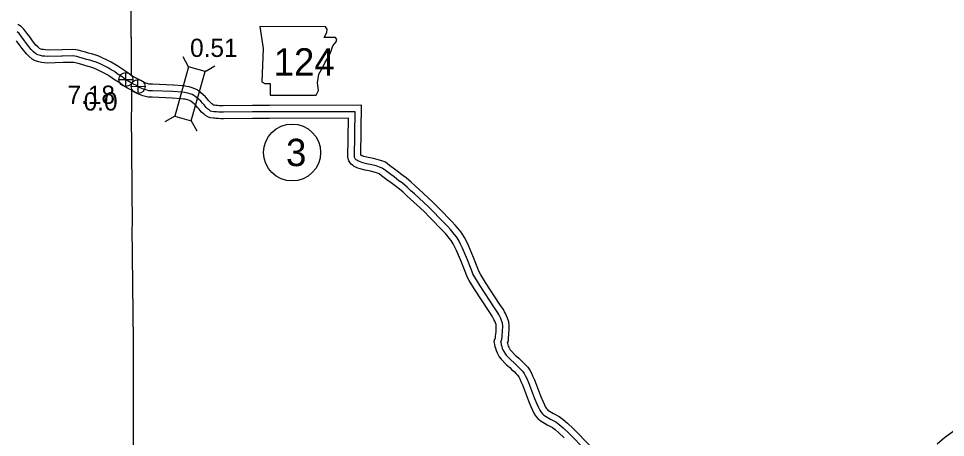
# Model space of a CAD drawing. Extents: x -83719 to 153526, y -11835 to 11446.
# Drawn here: x -664 to 52, y 1735 to 2059 of the extents above; entities that cross this region are included whole.
import ezdxf

# ---------------------------------------------------------------- set-up
doc = ezdxf.new("R2010")
doc.units = 0
for name, color, linetype in [('Level 10', 7, 'Continuous'), ('Level 11', 7, 'Continuous'), ('Level 2', 7, 'Continuous'), ('Level 20', 7, 'Continuous'), ('Level 21', 7, 'Continuous'), ('Level 25', 7, 'Continuous'), ('Level 26', 7, 'Continuous'), ('Level 27', 7, 'Continuous'), ('Level 58', 7, 'Continuous'), ('Level 59', 7, 'Continuous')]:
    doc.layers.add(name, color=color, linetype=linetype)

msp = doc.modelspace()

# ---------------------------------------------------------------- linework, layer by layer
at = {"layer": 'Level 10'}
for points in [[(-544.58, 2007.5), (-560.5, 2008.16), (-562.13, 2008.16), (-562.73, 2008.19), (-563.35, 2008.32), (-564.67, 2008.77), (-565.63, 2009.11), (-567.8, 2009.99), (-570.53, 2011.7), (-573.07, 2012.87), (-575.05, 2013.83), (-576.74, 2014.88)], [(-483.28, 1991.81), (-505.85, 1991.53), (-507.4, 1991.51), (-508.95, 1991.6), (-510.41, 1991.73), (-511.57, 1991.88), (-512.66, 1991.96), (-513.51, 1992.08), (-513.94, 1992.47), (-514.78, 1993.14), (-515.54, 1993.78), (-515.98, 1994.29), (-516.91, 1995.49), (-518.21, 1996.86), (-519.69, 1998.58), (-521.59, 2000.3), (-523.19, 2001.65), (-524.7, 2002.81), (-525.99, 2003.87), (-527.9, 2004.74), (-529.86, 2005.52), (-532.16, 2006.17), (-533.91, 2006.48), (-535.24, 2006.64), (-537.28, 2006.93), (-544.39, 2007.49)], [(-545, 1997.51), (-560.71, 1998.16), (-562.34, 1998.16), (-563.94, 1998.23), (-566, 1998.65), (-567.97, 1999.33), (-569.16, 1999.75), (-572.36, 2001.04), (-575.31, 2002.89), (-576.63, 2003.5)], [(-483.15, 1981.81), (-505.72, 1981.53), (-507.63, 1981.5), (-509.69, 1981.63), (-511.5, 1981.78), (-512.61, 1981.93), (-513.73, 1982.02), (-515.84, 1982.31), (-517.81, 1982.93), (-519.66, 1984.15), (-520.44, 1984.87), (-521.08, 1985.38), (-522.61, 1986.64), (-523.74, 1987.98), (-524.5, 1988.96), (-525.64, 1990.16), (-526.88, 1991.6), (-528.16, 1992.77), (-529.46, 1993.85), (-530.92, 1994.98), (-531.31, 1995.3), (-531.83, 1995.54), (-533.08, 1996.04), (-534.4, 1996.41), (-535.39, 1996.59), (-536.53, 1996.73), (-538.37, 1996.98), (-545.18, 1997.52)], [(-286.36, 1808.44), (-285.64, 1810.12), (-285.53, 1812.53), (-285.34, 1814.29), (-285.18, 1816.04), (-285.08, 1818.1), (-284.95, 1819.78), (-285.06, 1821.67), (-285.23, 1824.52), (-286.23, 1827.42), (-287.06, 1829.24), (-287.87, 1831), (-288.67, 1832.4), (-289.43, 1834.03), (-292.32, 1838.07), (-303.25, 1855.06), (-307.22, 1861.51), (-308.48, 1863.71), (-309.3, 1865.88), (-310.84, 1869.66), (-312.68, 1874.31), (-316.48, 1883.64), (-318.04, 1886.89), (-319.61, 1889.82), (-321.57, 1892.96), (-323.21, 1895.19), (-326.69, 1899.34), (-328.98, 1901.81), (-332.1, 1905.01), (-335.95, 1909.01), (-339.09, 1912.27), (-343.87, 1917.09), (-354.78, 1927.06), (-357.45, 1929.49), (-360.61, 1932.5), (-364.66, 1935.87), (-367.22, 1937.7), (-368.99, 1939), (-370.83, 1940.52), (-373.53, 1942.46), (-377.52, 1945.44), (-380.59, 1947.86), (-383.45, 1948.91), (-386.33, 1949.83), (-389.9, 1950.81), (-394.02, 1951.55), (-397.36, 1952.45), (-398.44, 1952.8), (-398.75, 1952.93), (-399.49, 1953.4), (-399.02, 1991.91), (-470.07, 1991.78), (-483.2, 1991.81)], [(-296.75, 1809.56), (-295.55, 1812.37), (-295.51, 1813.3), (-295.29, 1815.28), (-295.16, 1816.74), (-295.06, 1818.76), (-294.97, 1819.89), (-295.04, 1821.07), (-295.13, 1822.55), (-295.53, 1823.71), (-296.14, 1825.07), (-296.77, 1826.43), (-297.56, 1827.81), (-298.1, 1828.96), (-300.6, 1832.46), (-311.71, 1849.73), (-315.81, 1856.39), (-317.56, 1859.42), (-318.61, 1862.23), (-320.12, 1865.94), (-321.96, 1870.59), (-325.63, 1879.58), (-326.96, 1882.36), (-328.27, 1884.8), (-329.86, 1887.35), (-331.08, 1889.02), (-334.19, 1892.72), (-336.23, 1894.92), (-339.28, 1898.05), (-343.15, 1902.08), (-346.24, 1905.27), (-350.8, 1909.87), (-361.53, 1919.68), (-364.27, 1922.17), (-367.26, 1925.02), (-370.78, 1927.95), (-373.08, 1929.59), (-375.14, 1931.11), (-376.95, 1932.6), (-379.44, 1934.39), (-383.61, 1937.51), (-385.53, 1939.02), (-386.7, 1939.45), (-389.18, 1940.25), (-392.11, 1941.05), (-396.21, 1941.79), (-400.17, 1942.85), (-401.9, 1943.4), (-404.82, 1944.63), (-405.79, 1945.57), (-406.09, 1945.76), (-407.02, 1946.5), (-407.8, 1947.41), (-408.97, 1949.02), (-409.51, 1951.67), (-409.14, 1981.89), (-470.08, 1981.78), (-483.23, 1981.81)], [(-296.79, 1809.53), (-295.99, 1805.53), (-295.62, 1804.15), (-295.14, 1802.35), (-294.32, 1800.56), (-292.66, 1797.57), (-291.24, 1795.59), (-287.12, 1791.36), (-284.48, 1789.19), (-282.86, 1787.53), (-281.22, 1786.03), (-279.63, 1784.39), (-278.58, 1783.2), (-277.68, 1781.95), (-276.85, 1780.38), (-276.01, 1778.55), (-274.81, 1775.87), (-270.14, 1763.49), (-268.19, 1759.15), (-266.99, 1756.38), (-265.9, 1753.96), (-264.68, 1751.93), (-262.91, 1749.93), (-261.18, 1748.32), (-255.57, 1744.87), (-251.69, 1742.91), (-249.5, 1741.31), (-246.65, 1738.81), (-242.46, 1734.94)], [(-286.36, 1808.39), (-286.25, 1807.8), (-285.96, 1806.72), (-285.7, 1805.74), (-285.39, 1805.08), (-284.2, 1802.93), (-283.55, 1802.02), (-280.35, 1798.74), (-277.69, 1796.56), (-275.89, 1794.7), (-274.26, 1793.21), (-272.3, 1791.19), (-270.74, 1789.44), (-269.16, 1787.21), (-267.89, 1784.82), (-266.9, 1782.69), (-265.56, 1779.68), (-260.9, 1767.31), (-259.04, 1763.19), (-257.84, 1760.41), (-257.03, 1758.61), (-256.58, 1757.87), (-255.75, 1756.93), (-255.09, 1756.32), (-250.69, 1753.6), (-246.47, 1751.48), (-243.24, 1749.13), (-239.95, 1746.24), (-235.49, 1742.1), (-222.17, 1728.47)], [(45.47, 1730.23), (51.27, 1735.24), (69.75, 1748.55)]]:
    msp.add_lwpolyline(points, dxfattribs=at)
at = {"layer": 'Level 11'}
for points in [[(-576.63, 2014.81), (-577.13, 2015.12), (-579.64, 2017), (-581.16, 2018.1), (-584.97, 2020.5), (-587.17, 2022.08), (-589.81, 2023.69), (-592.4, 2025.29), (-596.03, 2027.07), (-598.78, 2028.42), (-602.03, 2029.79), (-604.93, 2030.88), (-607.52, 2031.61), (-610.04, 2032.25), (-612.32, 2032.95), (-615.31, 2033.8), (-617.78, 2034.4), (-619.58, 2034.76), (-622.06, 2035.06), (-630.09, 2034.9), (-641.18, 2034.61), (-643.08, 2034.78), (-644.79, 2034.95), (-645.89, 2035.16), (-647.19, 2035.55), (-647.76, 2035.87), (-649.17, 2037.08), (-650.5, 2038.34), (-653.1, 2041.66), (-655.3, 2044.78), (-657.48, 2047.67), (-659.86, 2050.83), (-661.94, 2052.69), (-664.47, 2054.26)], [(-576.45, 2003.42), (-577.34, 2003.83), (-579.88, 2005.05), (-582.79, 2006.86), (-585.56, 2008.95), (-586.75, 2009.8), (-590.56, 2012.2), (-592.7, 2013.74), (-595.05, 2015.17), (-597.25, 2016.53), (-600.42, 2018.09), (-602.92, 2019.31), (-605.73, 2020.49), (-608.06, 2021.37), (-610.1, 2021.95), (-612.74, 2022.61), (-615.16, 2023.36), (-617.86, 2024.13), (-619.95, 2024.64), (-621.16, 2024.88), (-622.55, 2025.05), (-629.86, 2024.9), (-641.49, 2024.6), (-644, 2024.82), (-646.23, 2025.04), (-648.28, 2025.43), (-651.14, 2026.3), (-653.53, 2027.65), (-655.86, 2029.64), (-657.91, 2031.58), (-661.13, 2035.69), (-663.39, 2038.89), (-665.46, 2041.66)]]:
    msp.add_lwpolyline(points, dxfattribs=at)
at = {"layer": 'Level 2'}
for points in [[(-576.62, 2016.42), (-576.93, 2073.47), (-577, 2075.21), (-577.8, 2161.28), (-577.83, 2163.01), (-578.77, 2249.01), (-578.7, 2250.72), (-579.42, 2288.6)], [(-576.61, 2015.07), (-576.93, 2073.47), (-577, 2075.21), (-577.8, 2161.28), (-577.83, 2163.01), (-578.77, 2249.01), (-578.7, 2250.72), (-579.42, 2288.6)], [(-575.21, 1721.72), (-575.14, 1809.64), (-576.15, 1897.51), (-575.94, 1898.88), (-576.63, 1985.79), (-576.46, 1987.3), (-576.55, 2003.27)], [(-575.21, 1721.72), (-575.14, 1809.64), (-576.15, 1897.51), (-575.94, 1898.88), (-576.63, 1985.79), (-576.46, 1987.3), (-576.54, 2002.28)]]:
    msp.add_lwpolyline(points, dxfattribs=at)
at = {"layer": 'Level 20'}
for p, q in [((-532.62, 2021.67), (-536.93, 2029.34)), ((-519.91, 2018.1), (-512.24, 2022.41)), ((-543.33, 1983.55), (-551, 1979.24)), ((-530.62, 1979.98), (-526.32, 1972.3))]:
    msp.add_line(p, q, dxfattribs=at)
msp.add_lwpolyline([(-532.62, 2021.67), (-543.33, 1983.55), (-530.62, 1979.98), (-519.91, 2018.1)], close=True, dxfattribs=at)
at = {"layer": 'Level 21'}
msp.add_lwpolyline([(-477.51, 2052.7), (-474.97, 2035.78), (-476.1, 2010.12), (-473.84, 2008.71), (-469.61, 2008.71), (-469.61, 1999.69), (-434.09, 1999.69), (-432.39, 2003.35), (-432.96, 2009.27), (-432.11, 2016.04), (-429.01, 2021.4), (-427.04, 2025.35), (-424.22, 2029.58), (-422.53, 2034.09), (-421.12, 2037.75), (-418.58, 2040.85), (-418.01, 2042.83), (-419.14, 2044.24), (-427.88, 2044.24), (-425.91, 2048.19), (-425.63, 2050.72), (-426.8, 2052.67)], close=True, dxfattribs=at)
at = {"layer": 'Level 26'}
for p, q in [((-586.43, 2011.85), (-575.6, 2011.85)), ((-581.02, 2006.43), (-581.02, 2017.27)), ((-571.45, 2001.03), (-571.7, 2011.88)), ((-577, 2006.33), (-566.16, 2006.58))]:
    msp.add_line(p, q, dxfattribs=at)
for centre, radius in [((-581.02, 2011.85), 5.42), ((-571.58, 2006.46), 5.43)]:
    msp.add_circle(centre, radius, dxfattribs=at)
at = {"layer": 'Level 27'}
msp.add_circle((-452.65, 1955.45), 22, dxfattribs=at)
at = {"layer": 'Level 59'}
for points in [[(-575.25, 2008.37), (-577.46, 2009.44), (-579.96, 2010.99), (-582.6, 2012.98), (-583.95, 2013.95), (-587.77, 2016.35), (-589.93, 2017.91), (-592.43, 2019.43), (-594.82, 2020.91), (-598.23, 2022.58), (-600.85, 2023.87), (-603.88, 2025.14), (-606.5, 2026.12), (-608.81, 2026.78), (-611.39, 2027.43), (-613.74, 2028.15), (-616.59, 2028.96), (-618.86, 2029.52), (-620.37, 2029.82), (-622.31, 2030.05), (-629.97, 2029.9), (-641.34, 2029.61), (-643.54, 2029.8), (-645.51, 2029.99), (-647.08, 2030.3), (-649.16, 2030.92), (-650.65, 2031.76), (-652.51, 2033.36), (-654.21, 2034.96), (-657.12, 2038.68), (-659.35, 2041.84), (-661.47, 2044.67), (-663.56, 2047.43), (-664.95, 2048.67)], [(-544.79, 2002.51), (-560.6, 2003.16), (-562.24, 2003.16), (-563.34, 2003.21), (-564.68, 2003.48), (-566.32, 2004.05), (-567.4, 2004.43), (-570.08, 2005.51), (-572.92, 2007.29), (-575.21, 2008.35), (-577.46, 2009.44), (-579.96, 2010.99), (-582.6, 2012.98), (-583.95, 2013.95), (-587.77, 2016.35), (-589.93, 2017.91), (-592.43, 2019.43), (-594.82, 2020.91), (-598.23, 2022.58), (-600.85, 2023.87), (-603.88, 2025.14), (-606.5, 2026.12), (-608.81, 2026.78), (-611.39, 2027.43), (-613.74, 2028.15), (-616.59, 2028.96), (-618.86, 2029.52), (-620.37, 2029.82), (-622.31, 2030.05), (-629.97, 2029.9), (-630.83, 2029.88)], [(-544.79, 2002.51), (-560.6, 2003.16), (-562.24, 2003.16), (-563.34, 2003.21), (-564.68, 2003.48), (-566.32, 2004.05), (-567.4, 2004.43), (-570.08, 2005.51), (-572.92, 2007.29), (-575.21, 2008.35), (-576.65, 2009.05)], [(-483.21, 1986.81), (-505.78, 1986.53), (-507.52, 1986.51), (-509.32, 1986.61), (-510.96, 1986.76), (-512.09, 1986.91), (-513.19, 1986.99), (-514.73, 1987.2), (-515.64, 1987.49), (-516.58, 1988.11), (-517.19, 1988.67), (-517.93, 1989.26), (-519.08, 1990.21), (-519.86, 1991.13), (-520.71, 1992.22), (-521.93, 1993.51), (-523.28, 1995.09), (-524.87, 1996.54), (-526.33, 1997.75), (-527.81, 1998.9), (-528.65, 1999.59), (-529.86, 2000.14), (-531.47, 2000.78), (-533.28, 2001.29), (-534.65, 2001.54), (-535.89, 2001.68), (-537.83, 2001.96), (-544.79, 2002.51)], [(-291.57, 1808.96), (-290.6, 1811.25), (-290.52, 1812.92), (-290.32, 1814.79), (-290.17, 1816.39), (-290.07, 1818.43), (-289.96, 1819.83), (-290.05, 1821.37), (-290.18, 1823.54), (-290.88, 1825.56), (-291.6, 1827.15), (-292.32, 1828.71), (-293.11, 1830.1), (-293.77, 1831.5), (-296.46, 1835.26), (-307.48, 1852.4), (-311.51, 1858.95), (-313.02, 1861.56), (-313.96, 1864.05), (-315.48, 1867.8), (-317.32, 1872.45), (-321.05, 1881.61), (-322.5, 1884.63), (-323.94, 1887.31), (-325.72, 1890.16), (-327.15, 1892.1), (-330.44, 1896.03), (-332.61, 1898.37), (-335.69, 1901.53), (-339.55, 1905.55), (-342.67, 1908.77), (-347.34, 1913.48), (-358.16, 1923.37), (-360.86, 1925.83), (-363.94, 1928.76), (-367.72, 1931.91), (-370.15, 1933.65), (-372.07, 1935.05), (-373.89, 1936.56), (-376.49, 1938.43), (-380.57, 1941.47), (-383.06, 1943.44), (-385.08, 1944.18), (-387.76, 1945.04), (-391, 1945.93), (-395.12, 1946.67), (-398.77, 1947.65), (-400.17, 1948.1), (-402.02, 1948.87), (-402.66, 1949.5), (-403.17, 1949.83), (-403.54, 1950.12), (-403.88, 1950.52), (-404.28, 1951.08), (-404.5, 1952.14), (-404.08, 1986.9), (-470.07, 1986.78), (-483.21, 1986.81)], [(-291.57, 1808.96), (-291.12, 1806.66), (-290.79, 1805.44), (-290.42, 1804.04), (-289.86, 1802.82), (-288.43, 1800.25), (-287.39, 1798.81), (-283.74, 1795.05), (-281.08, 1792.88), (-279.38, 1791.12), (-277.74, 1789.62), (-275.96, 1787.79), (-274.66, 1786.32), (-273.42, 1784.58), (-272.37, 1782.6), (-271.46, 1780.62), (-270.19, 1777.78), (-265.52, 1765.4), (-263.62, 1761.17), (-262.42, 1758.4), (-261.46, 1756.28), (-260.63, 1754.9), (-259.33, 1753.43), (-258.14, 1752.32), (-253.13, 1749.23), (-249.08, 1747.19), (-246.37, 1745.22), (-243.3, 1742.52), (-238.97, 1738.52), (-225.78, 1725.01)]]:
    msp.add_lwpolyline(points, dxfattribs=at)

# ---------------------------------------------------------------- texts
at = {"layer": 'Level 21'}
msp.add_text('124', height=21.12, dxfattribs=at).set_placement((-466.91, 2014.89))
at = {"layer": 'Level 25'}
msp.add_text('0.0', height=14.08, dxfattribs=at).set_placement((-613.63, 1987.86))
at = {"layer": 'Level 27'}
msp.add_text('3', height=21.12, dxfattribs=at).set_placement((-457.37, 1944.89))
at = {"layer": 'Level 58'}
for s, p in [('0.51', (-531.46, 2029.29)), ('7.18', (-626.13, 1993.02))]:
    msp.add_text(s, height=14.08, dxfattribs=at).set_placement(p)

doc.saveas('drawing.dxf')
